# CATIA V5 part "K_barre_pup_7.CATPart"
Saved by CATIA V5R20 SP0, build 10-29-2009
Part number: barre_pup_7
Bounding box of the stored display mesh (mm): x -66.046 to -50.815, y -98.346 to -6.502, z -77.181 to 38.679
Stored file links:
  G:\Khaled_CFAO_2011\ST2M\ST2M_GR2\gcausse\Khaled\CAD_ThinkMotion\K_barre_pup_7.CATPart
  C:\Documents and Settings\gcausse\Bureau\video thinkmotio\assemblage_gcausse\pupitre_think.CATProduct
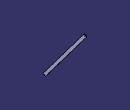
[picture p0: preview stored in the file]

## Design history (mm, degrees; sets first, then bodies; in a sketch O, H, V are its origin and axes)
Set1
  Sketch1 on Plane1, origin (-54.7303, 0, 6.7329), H (0, 1, 0), V (0.1221, 0, 0.9925)
    line L1 (-7.0269, 28.0302) -> (-93.8745, -83.583)
    arc A1 centre (-95.8475, -82.0477) radius 2.5 from (-93.8745, -83.583) to (-97.8206, -80.5125) cw
    point P3 (-95.8475, -82.0477)
    line L2 (-97.8206, -80.5125) -> (-10.9731, 31.1007)
    arc A2 centre (-9, 29.5654) radius 2.5 from (-10.9731, 31.1007) to (-7.0269, 28.0302) cw
    point P6 (-9, 29.5654)
    reference projected point E1 (-95.8475, -82.0477) from Point1
    reference projected point E2 (-9, 29.5654) from Point2
    reference projected line E3 (-9, 29.5654) -> (-95.8475, -82.0477) from Line1
    distance L2 L1 = 5
    tangency: A1 L1, L2 A1, A2 L1, A2 L2
    coincidence: P3 E1, P6 E2
    parallelism: L2 E3
Set2
  Plane1: linked copy from another document
  Point1: linked copy from another document
  Point2: linked copy from another document
  Line1: linked copy from another document
Body1 (main body)
  Pad1: profile Sketch1, direction (0.9925, 0, -0.1221), length -1
  Sketch2 on end face of Pad1, origin (-62.5687, -74.8739, -48.7938), H (0.1221, 0, 0.9925), V (0, 1, 0)
    point P1 (-25.9795, -20.9736)
    reference projected point E1 (-25.9795, -20.9736) from Point1
    coincidence: P1 E1
  Hole1: placed by Sketch2, at (-65.7408, -95.8475, -74.5789) direction (0.9925, 0, -0.1221), diameter 1, depth 1
  Sketch3 on end face of Pad1, origin (-62.4198, -73.1029, -47.5827), H (0.1221, 0, 0.9925), V (0, 1, 0)
    point P1 (84.4135, 64.1029)
    reference projected point E1 (84.4135, 64.1029) from Point2
    coincidence: P1 E1
  Hole2: placed by Sketch3, at (-52.113, -9, 36.1992) direction (0.9925, 0, -0.1221), diameter 1, depth 1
